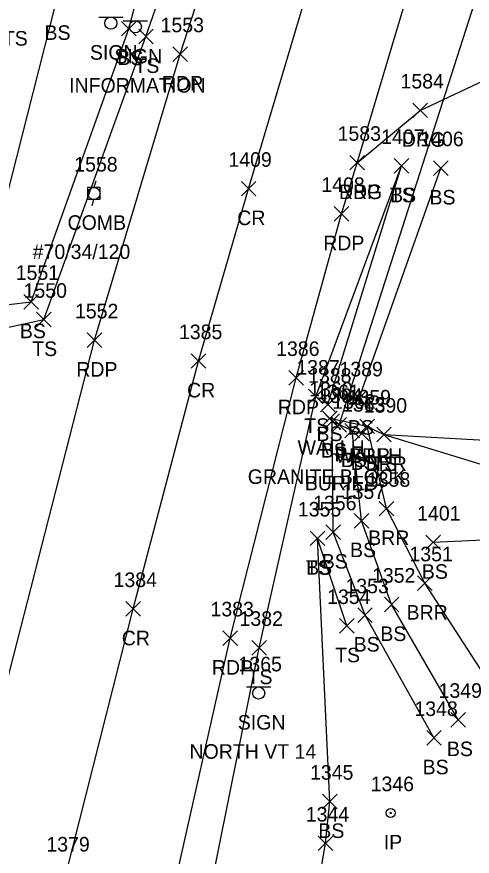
# Model space of a CAD drawing. Extents: x 1654425 to 1656893, y 667839 to 678429.
# Drawn here: x 1654625.8 to 1654688.3, y 668502.8 to 668618 of the extents above; entities that cross this region are included whole.
import ezdxf

# ---------------------------------------------------------------- set-up
doc = ezdxf.new("R2010")
doc.units = 0
for name, color, linetype in [('D_A', 7, 'Continuous'), ('D_C', 7, 'Continuous'), ('D_I', 7, 'Continuous'), ('D_TIC', 7, 'Continuous'), ('DCP', 7, 'Continuous'), ('DHW', 7, 'Continuous'), ('L_A', 7, 'Continuous'), ('L_I', 7, 'Continuous'), ('L_TIC', 7, 'Continuous'), ('LABL', 7, 'Continuous'), ('LELB', 7, 'Continuous'), ('M_A', 7, 'Continuous'), ('M_I', 7, 'Continuous'), ('MPIR', 7, 'Continuous'), ('P_A', 7, 'Continuous'), ('P_I', 7, 'Continuous'), ('P_TIC', 7, 'Continuous'), ('PET', 7, 'Continuous'), ('PRC', 7, 'Continuous'), ('R_A', 7, 'Continuous'), ('R_I', 7, 'Continuous'), ('R_TIC', 7, 'Continuous'), ('RDG', 7, 'Continuous'), ('S_A', 7, 'Continuous'), ('S_C', 7, 'Continuous'), ('S_I', 7, 'Continuous'), ('SSGN', 7, 'Continuous'), ('U_A', 7, 'Continuous'), ('U_C', 7, 'Continuous'), ('U_I', 7, 'Continuous'), ('UP', 7, 'Continuous')]:
    doc.layers.add(name, color=color, linetype=linetype)

msp = doc.modelspace()

# ---------------------------------------------------------------- linework, layer by layer
at = {"layer": 'D_TIC'}
for points in [[(1654667.74, 668561.91), (1654669.74, 668563.91)], [(1654669.74, 668561.91), (1654667.74, 668563.91)], [(1654669.02, 668561.02), (1654671.02, 668563.02)], [(1654671.02, 668561.02), (1654669.02, 668563.02)], [(1654672.89, 668560.81), (1654674.89, 668562.81)], [(1654674.89, 668560.81), (1654672.89, 668562.81)]]:
    msp.add_lwpolyline(points, dxfattribs=at)
at = {"layer": 'DCP'}
msp.add_lwpolyline([(1654670.02, 668562.02), (1654698.87, 668652)], dxfattribs=at)
at = {"layer": 'DHW'}
msp.add_lwpolyline([(1654673.89, 668561.81), (1654668.74, 668562.91)], dxfattribs=at)
at = {"layer": 'L_TIC'}
for points in [[(1654640.17, 668615.39), (1654642.17, 668617.39)], [(1654642.17, 668615.39), (1654640.17, 668617.39)], [(1654642.54, 668614.31), (1654644.54, 668616.31)], [(1654644.54, 668614.31), (1654642.54, 668616.31)], [(1654677.58, 668596.56), (1654679.58, 668598.56)], [(1654679.58, 668596.56), (1654677.58, 668598.56)], [(1654677.58, 668596.56), (1654679.58, 668598.56)], [(1654679.58, 668596.56), (1654677.58, 668598.56)], [(1654682.98, 668596.26), (1654684.98, 668598.26)], [(1654684.98, 668596.26), (1654682.98, 668598.26)], [(1654626.8, 668577.91), (1654628.8, 668579.91)], [(1654628.8, 668577.91), (1654626.8, 668579.91)], [(1654628.53, 668575.46), (1654630.53, 668577.46)], [(1654630.53, 668575.46), (1654628.53, 668577.46)], [(1654665.85, 668564.91), (1654667.85, 668566.91)], [(1654667.85, 668564.91), (1654665.85, 668566.91)], [(1654671.78, 668564.67), (1654673.78, 668566.67)], [(1654673.78, 668564.67), (1654671.78, 668566.67)], [(1654667.47, 668563.79), (1654669.47, 668565.79)], [(1654669.47, 668563.79), (1654667.47, 668565.79)], [(1654668.08, 668561.53), (1654670.08, 668563.53)], [(1654670.08, 668561.53), (1654668.08, 668563.53)], [(1654672.89, 668560.81), (1654674.89, 668562.81)], [(1654674.89, 668560.81), (1654672.89, 668562.81)], [(1654670.82, 668560.22), (1654672.82, 668562.22)], [(1654672.82, 668560.22), (1654670.82, 668562.22)], [(1654670.82, 668560.22), (1654672.82, 668562.22)], [(1654672.82, 668560.22), (1654670.82, 668562.22)], [(1654672.16, 668559.83), (1654674.16, 668561.83)], [(1654674.16, 668559.83), (1654672.16, 668561.83)], [(1654675.18, 668559.69), (1654677.18, 668561.69)], [(1654677.18, 668559.69), (1654675.18, 668561.69)], [(1654675.18, 668559.69), (1654677.18, 668561.69)], [(1654677.18, 668559.69), (1654675.18, 668561.69)], [(1654675.53, 668549.52), (1654677.53, 668551.52)], [(1654677.53, 668549.52), (1654675.53, 668551.52)], [(1654672.09, 668547.86), (1654674.09, 668549.86)], [(1654674.09, 668547.86), (1654672.09, 668549.86)], [(1654668.21, 668546.29), (1654670.21, 668548.29)], [(1654670.21, 668546.29), (1654668.21, 668548.29)], [(1654666.06, 668545.44), (1654668.06, 668547.44)], [(1654668.06, 668545.44), (1654666.06, 668547.44)], [(1654666.06, 668545.44), (1654668.06, 668547.44)], [(1654668.06, 668545.44), (1654666.06, 668547.44)], [(1654681.94, 668544.89), (1654683.94, 668546.89)], [(1654683.94, 668544.89), (1654681.94, 668546.89)], [(1654680.79, 668539.29), (1654682.79, 668541.29)], [(1654682.79, 668539.29), (1654680.79, 668541.29)], [(1654676.23, 668536.35), (1654678.23, 668538.35)], [(1654678.23, 668536.35), (1654676.23, 668538.35)], [(1654672.58, 668534.9), (1654674.58, 668536.9)], [(1654674.58, 668534.9), (1654672.58, 668536.9)], [(1654670.07, 668533.43), (1654672.07, 668535.43)], [(1654672.07, 668533.43), (1654670.07, 668535.43)], [(1654658.06, 668530.43), (1654660.06, 668532.43)], [(1654660.06, 668530.43), (1654658.06, 668532.43)], [(1654685.37, 668520.55), (1654687.37, 668522.55)], [(1654687.37, 668520.55), (1654685.37, 668522.55)], [(1654682.04, 668518.06), (1654684.04, 668520.06)], [(1654684.04, 668518.06), (1654682.04, 668520.06)], [(1654667.74, 668509.32), (1654669.74, 668511.32)], [(1654669.74, 668509.32), (1654667.74, 668511.32)], [(1654667.15, 668503.58), (1654669.15, 668505.58)], [(1654669.15, 668503.58), (1654667.15, 668505.58)]]:
    msp.add_lwpolyline(points, dxfattribs=at)
at = {"layer": 'LABL'}
msp.add_lwpolyline([(1654727.47, 668448.66), (1654723.77, 668470.01), (1654697.39, 668511.78), (1654690.89, 668526.25), (1654681.79, 668540.29), (1654676.53, 668550.52), (1654673.89, 668561.81), (1654676.18, 668560.69), (1654702.29, 668559.21), (1654719.79, 668550.09), (1654734.69, 668533.56)], dxfattribs=at)
at = {"layer": 'LELB'}
for points in [[(1654581.88, 668581.9), (1654606.98, 668576.45), (1654627.8, 668578.91), (1654641.17, 668616.39), (1654649.87, 668649.23), (1654649.52, 668665.58), (1654651.97, 668671.89), (1654662.51, 668696.29), (1654672.37, 668724.45), (1654685.62, 668761.8), (1654697.84, 668800.3), (1654711.19, 668841.94), (1654722.77, 668879.71)], [(1654622.64, 668586.29), (1654631.18, 668619.85), (1654637.57, 668649.9), (1654638.19, 668671.12), (1654637.91, 668695.82)], [(1654581.88, 668581.9), (1654607.43, 668571.66), (1654629.53, 668576.46), (1654643.54, 668615.31), (1654655.17, 668648.77)], [(1654627.02, 668380.04), (1654635.38, 668394.96), (1654638.88, 668406.25), (1654642.53, 668429.62), (1654644.5, 668453.08), (1654652.12, 668496.86), (1654659.06, 668531.43), (1654666.85, 668565.91), (1654678.58, 668597.56)], [(1654668.47, 668564.79), (1654678.58, 668597.56)], [(1654672.78, 668565.67), (1654683.98, 668597.26)], [(1654683.04, 668519.06), (1654673.58, 668535.9), (1654669.21, 668547.29), (1654669.08, 668562.53), (1654671.82, 668561.22), (1654673.16, 668560.83)], [(1654686.37, 668521.55), (1654677.23, 668537.35), (1654673.09, 668548.86), (1654671.82, 668561.22)], [(1654676.18, 668560.69), (1654698.87, 668553.72), (1654719.79, 668550.09)], [(1654730.96, 668520.24), (1654718.52, 668522.19), (1654719.24, 668535.59), (1654706.49, 668546.99), (1654682.94, 668545.89)], [(1654632.09, 668378.26), (1654647.7, 668382.66), (1654658.31, 668401.62), (1654653.52, 668410.41), (1654654.39, 668425.58), (1654665.51, 668489.09), (1654668.15, 668504.58), (1654668.74, 668510.32), (1654667.06, 668546.44)], [(1654671.07, 668534.43), (1654667.06, 668546.44)]]:
    msp.add_lwpolyline(points, dxfattribs=at)
at = {"layer": 'MPIR'}
for radius in [0.625, 0.0833]:
    msp.add_circle((1654677.1, 668508.74), radius, dxfattribs=at)
at = {"layer": 'P_TIC'}
for points in [[(1654647.24, 668611.9), (1654649.24, 668613.9)], [(1654649.24, 668611.9), (1654647.24, 668613.9)], [(1654671.51, 668597), (1654673.51, 668599)], [(1654673.51, 668597), (1654671.51, 668599)], [(1654656.62, 668593.43), (1654658.62, 668595.43)], [(1654658.62, 668593.43), (1654656.62, 668595.43)], [(1654669.36, 668589.98), (1654671.36, 668591.98)], [(1654671.36, 668589.98), (1654669.36, 668591.98)], [(1654635.49, 668572.63), (1654637.49, 668574.63)], [(1654637.49, 668572.63), (1654635.49, 668574.63)], [(1654649.75, 668569.78), (1654651.75, 668571.78)], [(1654651.75, 668569.78), (1654649.75, 668571.78)], [(1654663.14, 668567.47), (1654665.14, 668569.47)], [(1654665.14, 668567.47), (1654663.14, 668569.47)], [(1654640.79, 668535.76), (1654642.79, 668537.76)], [(1654642.79, 668535.76), (1654640.79, 668537.76)], [(1654654.08, 668531.73), (1654656.08, 668533.73)], [(1654656.08, 668531.73), (1654654.08, 668533.73)]]:
    msp.add_lwpolyline(points, dxfattribs=at)
at = {"layer": 'PET'}
for points in [[(1654621.12, 668380.08), (1654629.57, 668415.34), (1654638.69, 668455.31), (1654647.1, 668497.17), (1654655.08, 668532.73), (1654664.14, 668568.47), (1654670.36, 668590.98), (1654672.51, 668598), (1654685.45, 668641.36), (1654697.27, 668678.88), (1654709.65, 668714.91), (1654724.45, 668757.78), (1654737.22, 668795.28), (1654745.33, 668819.59), (1654761.32, 668866.34)], [(1654621.12, 668380.08), (1654605.24, 668384.01), (1654589.51, 668387.16), (1654598.99, 668428.03), (1654608.32, 668463.46), (1654620, 668509.52), (1654636.49, 668573.63), (1654648.24, 668612.9), (1654659.58, 668647.93)]]:
    msp.add_lwpolyline(points, dxfattribs=at)
at = {"layer": 'PRC'}
msp.add_lwpolyline([(1654605.24, 668384.01), (1654612.68, 668416.68), (1654623.19, 668461.23), (1654632.58, 668500.46), (1654641.79, 668536.76), (1654650.75, 668570.78), (1654657.62, 668594.43), (1654672.71, 668645.31)], dxfattribs=at)
at = {"layer": 'R_TIC'}
for points in [[(1654680.14, 668604.18), (1654682.14, 668606.18)], [(1654682.14, 668604.18), (1654680.14, 668606.18)], [(1654671.51, 668597), (1654673.51, 668599)], [(1654673.51, 668597), (1654671.51, 668599)]]:
    msp.add_lwpolyline(points, dxfattribs=at)
at = {"layer": 'RDG'}
msp.add_lwpolyline([(1654672.51, 668598), (1654681.14, 668605.18), (1654692.29, 668610.4), (1654724.97, 668607.76)], dxfattribs=at)
at = {"layer": 'SSGN'}
for p, q in [((1654637.06, 668617.98), (1654640.4, 668617.98)), ((1654638.71, 668617.15), (1654638.71, 668617.15)), ((1654640.42, 668617.47), (1654643.75, 668617.47)), ((1654642.07, 668616.63), (1654642.07, 668616.63)), ((1654657.34, 668526.05), (1654660.68, 668526.05)), ((1654658.99, 668525.21), (1654658.99, 668525.21))]:
    msp.add_line(p, q, dxfattribs=at)
for centre in [(1654638.71, 668617.15), (1654642.07, 668616.63), (1654658.99, 668525.21)]:
    msp.add_circle(centre, 0.833, dxfattribs=at)
at = {"layer": 'UP'}
for p, q in [((1654636.65, 668595.45), (1654636.4, 668594.62)), ((1654635.56, 668592.95), (1654635.56, 668594.62)), ((1654635.56, 668594.62), (1654637.23, 668594.62)), ((1654637.23, 668594.62), (1654637.23, 668592.95)), ((1654637.23, 668592.95), (1654635.56, 668592.95)), ((1654636.15, 668592.12), (1654636.4, 668592.95)), ((1654636.4, 668593.78), (1654636.4, 668593.78))]:
    msp.add_line(p, q, dxfattribs=at)
msp.add_circle((1654636.4, 668593.78), 0.833, dxfattribs=at)

# ---------------------------------------------------------------- texts
at = {"layer": 'D_A'}
for s, p in [('WALLH', (1654664.33, 668557.91)), ('WALLH', (1654669.48, 668556.81)), ('P', (1654669.4, 668557.02))]:
    msp.add_text(s, height=2, dxfattribs=at).set_placement(p)
at = {"layer": 'D_C'}
for s, p in [('GRANITE BLOCK', (1654657.5, 668553.91)), ('BURIED', (1654665.32, 668553.02))]:
    msp.add_text(s, height=2, dxfattribs=at).set_placement(p)
at = {"layer": 'D_I'}
for s, p in [('1360', (1654665.92, 668565.91)), ('1364', (1654667.28, 668565.02)), ('1359', (1654671.19, 668564.81))]:
    msp.add_text(s, height=2, dxfattribs=at).set_placement(p)
at = {"layer": 'L_A'}
for s, p in [('BS', (1654629.62, 668614.85)), ('TS', (1654623.9, 668614.06)), ('BS', (1654639.61, 668611.39)), ('TS', (1654641.95, 668610.31)), ('TS', (1654676.99, 668592.56)), ('BS', (1654677.02, 668592.56)), ('BS', (1654682.42, 668592.26)), ('BS', (1654626.24, 668573.91)), ('TS', (1654627.94, 668571.46)), ('TS', (1654665.26, 668560.91)), ('BS', (1654666.92, 668559.79)), ('BS', (1654671.22, 668560.67)), ('BS', (1654667.52, 668557.53)), ('BS', (1654670.26, 668556.22)), ('BS', (1654670.26, 668556.22)), ('BRR', (1654671.38, 668556.81)), ('BS', (1654671.6, 668555.83)), ('BRR', (1654673.66, 668555.69)), ('TS', (1654674.59, 668555.69)), ('BRR', (1654674.02, 668545.52)), ('BS', (1654671.53, 668543.86)), ('BS', (1654667.65, 668542.29)), ('TS', (1654665.47, 668541.44)), ('BS', (1654665.5, 668541.44)), ('BS', (1654681.38, 668540.89)), ('BRR', (1654679.28, 668535.29)), ('BS', (1654675.68, 668532.35)), ('BS', (1654672.02, 668530.9)), ('TS', (1654669.48, 668529.43)), ('TS', (1654657.47, 668526.43)), ('BS', (1654684.81, 668516.55)), ('BS', (1654681.48, 668514.06)), ('BS', (1654667.18, 668505.32))]:
    msp.add_text(s, height=2, dxfattribs=at).set_placement(p)
at = {"layer": 'L_I'}
for s, p in [('1407', (1654675.8, 668600.56)), ('1407', (1654675.8, 668600.56)), ('1406', (1654681.16, 668600.26)), ('1551', (1654625.67, 668581.91)), ('1550', (1654626.75, 668579.46)), ('1387', (1654664.16, 668568.91)), ('1388', (1654665.78, 668567.79)), ('1389', (1654670.08, 668568.67)), ('1361', (1654666.9, 668565.53)), ('1362', (1654669.08, 668564.22)), ('1362', (1654669.08, 668564.22)), ('1359', (1654671.19, 668564.81)), ('1363', (1654670.42, 668563.83)), ('1390', (1654673.4, 668563.69)), ('1390', (1654673.4, 668563.69)), ('1358', (1654673.84, 668553.52)), ('1357', (1654670.39, 668551.86)), ('1355', (1654664.37, 668549.44)), ('1355', (1654664.37, 668549.44)), ('1356', (1654666.46, 668550.29)), ('1401', (1654680.73, 668548.89)), ('1351', (1654679.67, 668543.29)), ('1352', (1654674.54, 668540.35)), ('1353', (1654670.89, 668538.9)), ('1354', (1654668.38, 668537.43)), ('1382', (1654656.37, 668534.43)), ('1349', (1654683.67, 668524.55)), ('1348', (1654680.35, 668522.06)), ('1345', (1654666.04, 668513.32)), ('1344', (1654665.46, 668507.58))]:
    msp.add_text(s, height=2, dxfattribs=at).set_placement(p)
at = {"layer": 'M_A'}
msp.add_text('IP', height=2, dxfattribs=at).set_placement((1654676.15, 668503.74))
at = {"layer": 'M_I'}
msp.add_text('1346', height=2, dxfattribs=at).set_placement((1654674.35, 668511.74))
at = {"layer": 'P_A'}
for s, p in [('RDP', (1654645.72, 668607.9)), ('RDP', (1654670, 668593)), ('CR', (1654656.06, 668589.43)), ('RDP', (1654667.85, 668585.98)), ('RDP', (1654633.98, 668568.63)), ('CR', (1654649.18, 668565.78)), ('RDP', (1654661.62, 668563.47)), ('CR', (1654640.22, 668531.76)), ('RDP', (1654652.57, 668527.73))]:
    msp.add_text(s, height=2, dxfattribs=at).set_placement(p)
at = {"layer": 'P_I'}
for s, p in [('1553', (1654645.54, 668615.9)), ('1583', (1654669.82, 668601)), ('1409', (1654654.84, 668597.43)), ('1408', (1654667.59, 668593.98)), ('1552', (1654633.8, 668576.63)), ('1385', (1654648.06, 668573.78)), ('1386', (1654661.39, 668571.47)), ('1384', (1654639.09, 668539.76)), ('1383', (1654652.39, 668535.73)), ('1379', (1654629.88, 668503.46))]:
    msp.add_text(s, height=2, dxfattribs=at).set_placement(p)
at = {"layer": 'R_A'}
for p in [(1654678.63, 668600.18), (1654670, 668593)]:
    msp.add_text('DRG', height=2, dxfattribs=at).set_placement(p)
at = {"layer": 'R_I'}
for s, p in [('1584', (1654678.45, 668608.18)), ('1583', (1654669.82, 668601))]:
    msp.add_text(s, height=2, dxfattribs=at).set_placement(p)
at = {"layer": 'S_A'}
for p in [(1654635.85, 668612.13), (1654639.21, 668611.61), (1654656.13, 668520.19)]:
    msp.add_text('SIGN', height=2, dxfattribs=at).set_placement(p)
at = {"layer": 'S_C'}
for s, p in [('INFORMATION', (1654633, 668607.61)), ('NORTH VT 14', (1654649.51, 668516.19))]:
    msp.add_text(s, height=2, dxfattribs=at).set_placement(p)
at = {"layer": 'S_I'}
msp.add_text('1365', height=2, dxfattribs=at).set_placement((1654656.23, 668528.19))
at = {"layer": 'U_A'}
msp.add_text('COMB', height=2, dxfattribs=at).set_placement((1654632.78, 668588.78))
at = {"layer": 'U_C'}
msp.add_text('#70/34/120', height=2, dxfattribs=at).set_placement((1654628, 668584.78))
at = {"layer": 'U_I'}
msp.add_text('1558', height=2, dxfattribs=at).set_placement((1654633.7, 668596.78))

doc.saveas('drawing.dxf')
